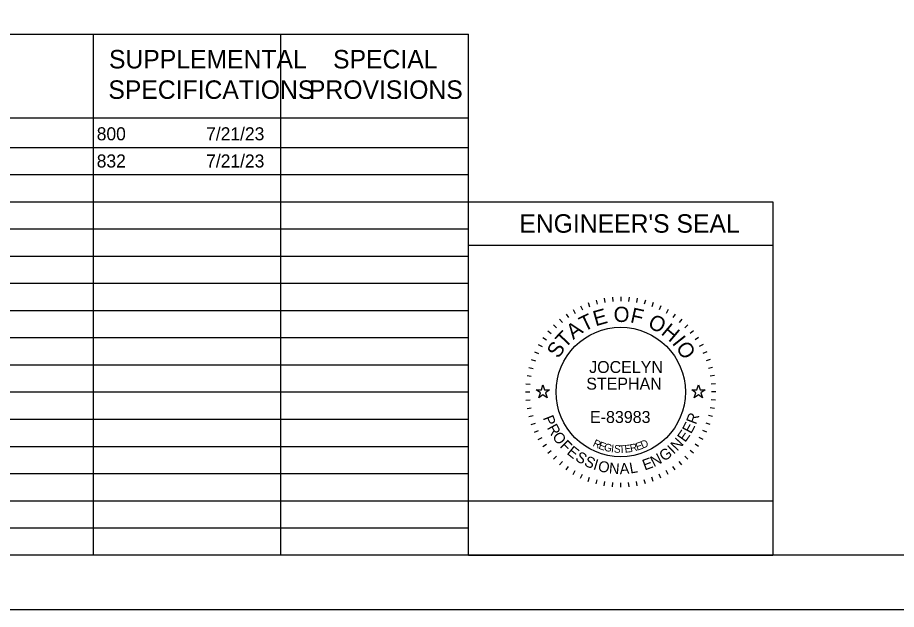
# Model space of a CAD drawing. Extents: x 0 to 34, y 0 to 22.
# Drawn here: x 20.38 to 28.46, y 0 to 5.44 of the extents above; entities that cross this region are included whole.
import ezdxf

# ---------------------------------------------------------------- set-up
doc = ezdxf.new("R2010")
doc.units = 0
for name, color, linetype in [('Default', 7, 'Continuous'), ('SH_Border', 7, 'Continuous'), ('SH_Cut_Line', 7, 'Continuous'), ('SH_Data', 7, 'Continuous'), ('SH_Text', 7, 'Continuous')]:
    doc.layers.add(name, color=color, linetype=linetype)

msp = doc.modelspace()

# ---------------------------------------------------------------- linework, layer by layer
at = {"layer": 'Default'}
for points in [[(25.1506, 2.02), (25.1975, 2.02), (25.212, 2.0645), (25.2265, 2.02), (25.2734, 2.02), (25.2355, 1.9924), (25.25, 1.9478), (25.212, 1.9754), (25.174, 1.9478), (25.1885, 1.9924)], [(26.5806, 2.02), (26.6275, 2.02), (26.642, 2.0645), (26.6565, 2.02), (26.7034, 2.02), (26.6655, 1.9924), (26.68, 1.9478), (26.642, 1.9754), (26.604, 1.9478), (26.6185, 1.9924)]]:
    msp.add_lwpolyline(points, close=True, dxfattribs=at)
at = {"layer": 'SH_Border'}
msp.add_lwpolyline([(1.5, 21.5), (33.5, 21.5), (33.5, 0.5), (1.5, 0.5)], close=True, dxfattribs=at)
at = {"layer": 'SH_Cut_Line'}
msp.add_lwpolyline([(0, 0), (34, 0), (34, 22), (0, 22)], close=True, dxfattribs=at)
at = {"layer": 'SH_Data'}
for p, q in [((11.077, 5.2918), (24.527, 5.2918)), ((21.077, 0.5), (21.077, 5.2918)), ((22.802, 0.5), (22.802, 5.2918)), ((24.527, 0.5), (24.527, 5.2918)), ((11.077, 4.5209), (24.527, 4.5209)), ((11.077, 4.25), (24.527, 4.25)), ((11.077, 4), (24.527, 4)), ((11.077, 3.75), (24.527, 3.75)), ((24.527, 0.5), (24.527, 3.75)), ((24.527, 3.75), (27.327, 3.75)), ((27.327, 3.75), (27.327, 0.5)), ((11.077, 3.5), (24.527, 3.5)), ((24.527, 3.35), (27.327, 3.35)), ((11.077, 3.25), (24.527, 3.25)), ((11.077, 3), (24.527, 3)), ((25.7005, 2.8452), (25.7109, 2.8065)), ((25.7751, 2.8617), (25.782, 2.8223)), ((25.8508, 2.8717), (25.8542, 2.8318)), ((25.927, 2.875), (25.927, 2.835)), ((26.0033, 2.8717), (25.9998, 2.8318)), ((26.079, 2.8617), (26.072, 2.8223)), ((26.1535, 2.8452), (26.1431, 2.8065)), ((11.077, 2.75), (24.527, 2.75)), ((25.4895, 2.7578), (25.5095, 2.7231)), ((25.5572, 2.793), (25.5741, 2.7568)), ((25.6277, 2.8222), (25.6414, 2.7846)), ((26.2263, 2.8222), (26.2126, 2.7846)), ((26.2968, 2.793), (26.2799, 2.7568)), ((26.3645, 2.7578), (26.3445, 2.7231)), ((25.3646, 2.6703), (25.3903, 2.6396)), ((25.4251, 2.7168), (25.4481, 2.684)), ((26.4289, 2.7168), (26.406, 2.684)), ((26.4895, 2.6703), (26.4637, 2.6396)), ((25.3083, 2.6187), (25.3366, 2.5904)), ((26.5457, 2.6187), (26.5174, 2.5904)), ((25.2567, 2.5624), (25.2874, 2.5367)), ((26.5973, 2.5624), (26.5667, 2.5367)), ((11.077, 2.5), (24.527, 2.5)), ((25.1692, 2.4375), (25.2039, 2.4175)), ((25.2103, 2.5019), (25.243, 2.4789)), ((26.6438, 2.5019), (26.611, 2.4789)), ((26.6848, 2.4375), (26.6501, 2.4175)), ((25.134, 2.3698), (25.1702, 2.3529)), ((26.72, 2.3698), (26.6838, 2.3529)), ((25.1048, 2.2993), (25.1424, 2.2856)), ((26.7492, 2.2993), (26.7117, 2.2856)), ((11.077, 2.25), (24.527, 2.25)), ((25.0818, 2.2265), (25.1205, 2.2161)), ((26.7722, 2.2265), (26.7336, 2.2161)), ((25.0653, 2.1519), (25.1047, 2.145)), ((26.7887, 2.1519), (26.7493, 2.145)), ((25.0553, 2.0763), (25.0952, 2.0728)), ((26.7987, 2.0763), (26.7588, 2.0728)), ((11.077, 2), (24.527, 2)), ((25.052, 2), (25.092, 2)), ((26.802, 2), (26.762, 2)), ((25.0553, 1.9237), (25.0952, 1.9272)), ((26.7987, 1.9237), (26.7588, 1.9272)), ((25.0653, 1.8481), (25.1047, 1.855)), ((25.0818, 1.7735), (25.1205, 1.7839)), ((26.7722, 1.7735), (26.7336, 1.7839)), ((26.7887, 1.8481), (26.7493, 1.855)), ((11.077, 1.75), (24.527, 1.75)), ((25.1048, 1.7007), (25.1424, 1.7144)), ((26.7492, 1.7007), (26.7117, 1.7144)), ((25.134, 1.6302), (25.1702, 1.6471)), ((26.72, 1.6302), (26.6838, 1.6471)), ((25.1692, 1.5625), (25.2039, 1.5825)), ((26.6848, 1.5625), (26.6501, 1.5825)), ((11.077, 1.5), (24.527, 1.5)), ((25.2103, 1.4981), (25.243, 1.5211)), ((25.2567, 1.4376), (25.2874, 1.4633)), ((26.5973, 1.4376), (26.5667, 1.4633)), ((26.6438, 1.4981), (26.611, 1.5211)), ((25.3083, 1.3813), (25.3366, 1.4096)), ((26.5457, 1.3813), (26.5174, 1.4096)), ((25.3646, 1.3297), (25.3903, 1.3604)), ((25.4251, 1.2832), (25.4481, 1.316)), ((26.4289, 1.2832), (26.406, 1.316)), ((26.4895, 1.3297), (26.4637, 1.3604)), ((11.077, 1.25), (24.527, 1.25)), ((25.4895, 1.2422), (25.5095, 1.2769)), ((25.5572, 1.207), (25.5741, 1.2432)), ((25.6277, 1.1778), (25.6414, 1.2154)), ((26.2263, 1.1778), (26.2126, 1.2154)), ((26.2968, 1.207), (26.2799, 1.2432)), ((26.3645, 1.2422), (26.3445, 1.2769)), ((25.7005, 1.1548), (25.7109, 1.1935)), ((25.7751, 1.1383), (25.782, 1.1777)), ((25.8508, 1.1283), (25.8542, 1.1682)), ((25.927, 1.125), (25.927, 1.165)), ((26.0033, 1.1283), (25.9998, 1.1682)), ((26.079, 1.1383), (26.072, 1.1777)), ((26.1535, 1.1548), (26.1431, 1.1935)), ((11.077, 1), (24.527, 1)), ((11.077, 0.75), (24.527, 0.75)), ((24.527, 0.5), (27.327, 0.5))]:
    msp.add_line(p, q, dxfattribs=at)
msp.add_lwpolyline([(24.527, 0.5), (24.527, 1), (27.327, 1), (27.327, 0.5)], close=True, dxfattribs=at)
msp.add_circle((25.927, 2), 0.595, dxfattribs=at)

# ---------------------------------------------------------------- texts
for s, height, p in [("ENGINEER'S SEAL", 0.17, (24.9946, 3.465)), ('JOCELYN', 0.11, (25.637, 2.1749)), ('STEPHAN', 0.11, (25.6101, 2.0216)), ('E-83983', 0.11, (25.6447, 1.7151))]:
    msp.add_text(s, height=height, dxfattribs=at).set_placement(p)
for s, height, rotation, p in [('E', 0.14, 15.75706, (25.6954, 2.6038)), ('O', 0.14, 359.78119, (25.8617, 2.6443)), ('F', 0.14, 347.43619, (26.0081, 2.6417)), ('T', 0.14, 25.71674, (25.5886, 2.5518)), ('O', 0.14, 332.25863, (26.1668, 2.6015)), ('A', 0.14, 36.47472, (25.4904, 2.4781)), ('H', 0.14, 319.91363, (26.2902, 2.5361)), ('T', 0.14, 46.4344, (25.4153, 2.3964)), ('I', 0.14, 308.36695, (26.3935, 2.4483)), ('S', 0.14, 57.19238, (25.3551, 2.3014)), ('O', 0.14, 303.14906, (26.4292, 2.4089)), ('P', 0.1, 291.49398, (25.2093, 1.7621)), ('R', 0.1, 69.23216, (26.619, 1.6954)), ('R', 0.1, 298.73106, (25.246, 1.6717)), ('E', 0.1, 61.99508, (26.5747, 1.6098)), ('O', 0.1, 306.46664, (25.2925, 1.5883)), ('E', 0.1, 54.75801, (26.5203, 1.5314)), ('F', 0.1, 314.7068, (25.3613, 1.4983)), ('R', 0.07, 334.48695, (25.6645, 1.5051)), ('E', 0.07, 341.03996, (25.7176, 1.4801)), ('E', 0.07, 17.68363, (26.0768, 1.4602)), ('D', 0.07, 23.30524, (26.128, 1.477)), ('N', 0.1, 47.02243, (26.4472, 1.4508)), ('E', 0.1, 321.43929, (25.4248, 1.4348)), ('G', 0.07, 347.47515, (25.7685, 1.4618)), ('I', 0.07, 353.78581, (25.8361, 1.4468)), ('S', 0.07, 356.89262, (25.8628, 1.4429)), ('T', 0.07, 3.00609, (25.9127, 1.4387)), ('E', 0.07, 6.01169, (25.966, 1.4412)), ('R', 0.07, 11.91844, (26.0195, 1.4474)), ('G', 0.1, 35.04687, (26.3251, 1.357)), ('I', 0.1, 43.28703, (26.4139, 1.4214)), ('S', 0.1, 328.67637, (25.5013, 1.3752)), ('S', 0.1, 335.91345, (25.5834, 1.3266)), ('I', 0.1, 343.15053, (25.6676, 1.2897)), ('E', 0.1, 20.07421, (26.1482, 1.277)), ('N', 0.1, 27.31129, (26.2315, 1.3075)), ('O', 0.1, 346.88592, (25.7109, 1.2751)), ('N', 0.1, 355.12608, (25.8158, 1.2517)), ('A', 0.1, 2.86166, (25.9193, 1.2437)), ('L', 0.1, 10.09874, (26.0164, 1.249))]:
    msp.add_text(s, height=height, rotation=rotation, dxfattribs=at).set_placement(p)
at = {"layer": 'SH_Text'}
for s, height, p in [('SUPPLEMENTAL', 0.17, (21.2195, 4.9763)), ('SPECIAL', 0.17, (23.2812, 4.9763)), ('SPECIFICATIONS', 0.17, (21.2141, 4.6963)), ('PROVISIONS', 0.17, (23.0593, 4.6963)), ('800     ', 0.12, (21.107, 4.315)), (' 7/21/23', 0.12, (22.069, 4.315)), ('832     ', 0.12, (21.107, 4.065)), (' 7/21/23', 0.12, (22.069, 4.065))]:
    msp.add_text(s, height=height, dxfattribs=at).set_placement(p)

doc.saveas('drawing.dxf')
